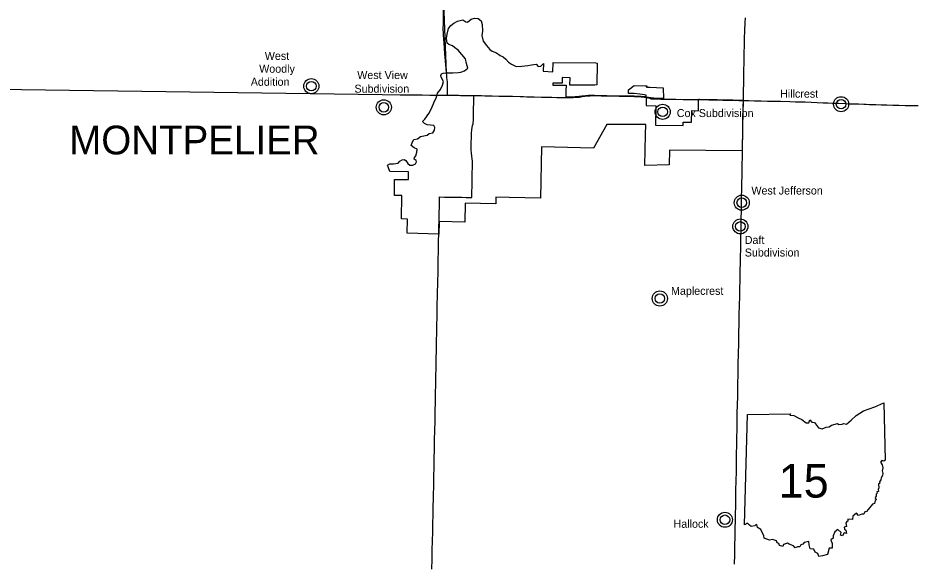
# Model space of a CAD drawing. Extents: x -66 to 795, y 0 to 440.
# Drawn here: x 250.6 to 383.6, y 175.4 to 256.3 of the extents above; entities that cross this region are included whole.
import ezdxf

# ---------------------------------------------------------------- set-up
doc = ezdxf.new("R2010")
doc.units = 0
for name, color, linetype in [('DV_X_Corp_Line', 7, 'Continuous'), ('GM_X_Corporation_Text', 7, 'Continuous'), ('GM_X_State_Route', 7, 'Continuous'), ('GM_X_US_Route', 7, 'Continuous'), ('PV_P_Text', 7, 'Continuous'), ('RD_P_Fence', 7, 'Continuous')]:
    doc.layers.add(name, color=color, linetype=linetype)

msp = doc.modelspace()

# ---------------------------------------------------------------- linework, layer by layer
at = {"layer": 'DV_X_Corp_Line'}
msp.add_lwpolyline([(358.16, 240.24), (358.16, 240.08), (358.12, 238.6), (358.11, 237.76), (358.11, 237.68), (358.1, 237.15), (358.1, 236.81), (358.09, 236.57), (347.3, 236.7), (347.25, 234.52), (343.65, 234.43), (343.75, 238.98), (343.78, 240.5), (337.99, 240.49), (336.03, 236.98), (328.3, 237.19), (328.17, 229.58), (323.52, 229.66), (321.55, 229.69), (321.54, 228.72), (316.97, 228.82), (316.93, 226), (313.12, 226.1), (313.12, 225.97), (313.11, 225.89), (313.08, 224.34), (313.08, 224.2), (308.36, 224.36), (308.41, 226.44), (307.55, 226.48), (307.59, 229.94), (306.49, 229.96), (306.51, 232.33), (308.58, 232.35), (308.56, 233.48), (305.82, 233.54), (305.61, 234.09), (305.47, 234.46), (305.8, 234.68), (306.33, 234.66), (307.02, 234.77), (307.28, 235.05), (307.63, 235.26), (307.92, 235.29), (308.16, 235.16), (308.46, 234.7), (308.78, 234.44), (309.23, 234.48), (309.6, 234.68), (309.73, 234.94), (309.69, 235.13), (309.39, 235.34), (309.45, 235.58), (309.65, 235.86), (309.78, 236.37), (309.87, 236.84), (309.42, 237.05), (308.96, 237.36), (309.17, 237.92), (309.35, 238.25), (309.9, 238.35), (310.34, 238.72), (311.33, 238.92), (311.65, 239.16), (312.16, 239.28), (312.45, 239.67), (312.48, 240.07), (312.33, 240.36), (311.82, 240.42), (311.34, 240.46), (310.94, 240.66), (310.73, 240.84), (310.66, 240.95), (311, 241.29), (311.58, 242.11), (311.97, 242.88), (312.33, 243.69), (312.67, 244.48), (312.81, 244.92), (312.89, 245.14), (313.33, 245.67), (313.63, 246.34), (313.78, 246.9), (313.43, 247.52), (313.39, 247.77), (313.47, 248), (313.7, 248.1), (314.22, 248.15), (314.21, 248.25), (314.29, 248.19), (315.14, 248.18), (315.99, 248.2), (316.35, 248.26), (316.87, 248.45), (317.38, 248.85), (317.19, 249.57), (317.05, 250.25), (316.49, 250.87), (315.92, 251.52), (315.4, 251.94), (315.12, 252.16), (314.56, 252.37), (314.29, 252.59), (314.21, 253.27), (314.33, 253.89), (314.51, 254.74), (314.84, 255.19), (315.29, 255.54), (315.84, 255.83), (316.62, 256.06), (317.07, 255.73), (317.3, 255.69), (317.86, 256.12), (318.38, 256.29), (318.9, 256.23), (319.34, 255.89), (319.52, 255.32), (319.54, 254.34), (319.45, 253.69), (319.63, 252.89), (320.15, 252.23), (320.63, 251.63), (320.98, 251.38), (321.63, 251.15), (322.19, 250.76), (322.61, 250.54), (323, 250.21), (323.39, 249.74), (323.86, 249.43), (324.55, 249.11), (325.39, 249.17), (326.29, 249.25), (326.81, 249.35), (327.18, 249.42), (327.52, 249.45), (327.81, 249.09), (328.21, 249.17), (328.6, 249.56), (328.57, 248.44), (330, 248.33), (330.02, 249.71), (336.35, 249.63), (336.56, 249.62), (336.5, 246.38), (336.23, 246.35), (332.53, 246.34), (332.55, 247.42), (331.37, 247.46), (331.37, 246.65), (330, 246.62), (330, 246.34), (331.97, 246.34), (331.93, 245.48), (331.91, 244.6), (332.38, 244.61), (332.76, 244.62), (333.28, 244.65), (333.44, 244.67), (334.3, 244.76), (334.44, 244.77), (334.83, 244.8), (335.27, 244.83), (335.59, 244.85), (336.19, 244.85), (338.02, 244.81), (340.06, 244.76), (341.15, 244.77), (342.07, 244.76), (343.09, 244.69), (343.61, 244.64), (343.84, 244.64), (343.85, 244.87), (343.57, 244.89), (342.91, 244.99), (342.07, 245.08), (341.23, 245.09), (341.24, 245.64), (342.04, 246.27), (343.68, 246.25), (343.92, 246.25), (343.91, 246.06), (344.37, 246.04), (346.38, 245.96), (346.43, 244.34), (346.2, 244.34), (345.24, 244.37), (344.96, 244.4), (344.51, 244.46), (343.87, 244.55), (343.86, 244.09), (343.85, 243.3), (345.27, 243.27), (345.23, 240.4), (349.35, 240.35), (349.35, 240.85), (350.59, 240.83), (350.63, 242.58), (351.61, 242.53), (351.62, 244.25), (351.76, 244.24), (352.16, 244.23), (353.14, 244.22), (354.37, 244.19), (355.66, 244.16), (356.68, 244.14), (357.6, 244.12), (358.23, 244.12)], close=True, dxfattribs=at)
for centre, radius in [((294.14, 246.19), 1.12), ((294.14, 246.19), 0.71), ((304.9, 243.05), 1.12), ((304.9, 243.05), 0.71), ((346.29, 242.38), 1.12), ((372.77, 243.51), 1.12), ((372.77, 243.51), 0.71), ((346.29, 242.38), 0.71), ((358.03, 228.89), 1.12), ((358.03, 228.89), 0.71), ((357.82, 225.37), 1.12), ((357.82, 225.37), 0.71), ((345.87, 214.67), 1.12), ((345.87, 214.67), 0.71), ((355.53, 181.82), 1.12), ((355.53, 181.82), 0.71)]:
    msp.add_circle(centre, radius, dxfattribs=at)
at = {"layer": 'GM_X_State_Route'}
msp.add_line((224.27, 246.03), (308.22, 244.92), dxfattribs=at)
for points in [[(314.22, 248.17), (314.16, 248.78), (314.06, 249.96), (313.97, 250.99), (313.91, 251.77), (313.84, 252.59), (313.79, 253.21), (313.76, 253.69), (313.74, 254.12), (313.73, 254.63), (313.74, 255.53), (313.77, 256.79), (313.79, 258.34), (313.81, 259.46), (313.81, 259.94), (313.81, 260.45), (313.85, 262.15), (313.88, 263.44), (313.91, 264.81), (313.93, 266), (313.95, 267.26), (313.98, 268.62), (314.01, 269.72), (314.02, 270.11)], [(314.38, 244.85), (314.38, 245.46), (314.38, 245.48), (314.37, 246.12), (314.37, 246.17), (314.36, 246.39), (314.34, 246.77), (314.34, 246.83), (314.28, 247.43), (314.25, 247.77), (314.22, 248.17), (314.22, 248.17)], [(307.31, 244.92), (307.31, 244.92), (308.22, 244.92), (309.36, 244.9), (310.6, 244.89), (311.75, 244.87), (312.46, 244.87), (312.53, 244.86), (312.53, 244.86)], [(312.53, 244.86), (312.84, 244.86), (312.84, 244.86)], [(312.84, 244.86), (313.14, 244.86), (313.15, 244.86)], [(313.15, 244.86), (313.45, 244.86), (314.38, 244.85)], [(314.38, 244.85), (315.05, 244.85), (315.26, 244.85), (316.03, 244.83), (316.28, 244.82), (316.98, 244.81), (317.22, 244.81), (318, 244.8), (318.26, 244.8)], [(317.97, 229.66), (317.99, 230.63), (318, 231.14), (318.01, 231.63), (318.02, 232.04), (318.03, 232.55), (318.03, 232.94), (318.04, 233.58), (318.05, 233.85), (318.06, 234.78), (318.05, 235.06), (318.02, 235.38), (317.96, 235.78), (317.91, 236.26), (317.88, 236.74), (317.86, 237.25), (317.87, 237.84), (317.9, 238.53), (317.94, 239.2), (317.97, 239.69), (318.01, 240.05), (318.06, 240.34), (318.15, 240.58), (318.19, 241.26), (318.21, 241.88), (318.21, 241.95), (318.22, 242.82), (318.24, 243.76), (318.24, 243.81), (318.26, 244.8)], [(318.26, 244.8), (319.03, 244.79), (319.27, 244.78), (319.4, 244.78), (319.91, 244.77), (320.05, 244.77), (320.21, 244.76), (320.99, 244.74), (321.99, 244.72), (322.19, 244.71), (322.73, 244.7), (323.08, 244.7), (323.75, 244.69), (323.98, 244.68), (325.15, 244.66), (325.21, 244.65), (325.63, 244.64), (325.64, 244.64)], [(331.97, 244.51), (332.99, 244.49), (333.93, 244.58), (334.34, 244.66), (334.76, 244.71), (335.28, 244.75), (335.54, 244.77), (336.17, 244.78), (337.18, 244.75), (338.03, 244.75), (338.66, 244.73), (339.85, 244.7), (341.01, 244.69), (341.16, 244.69)], [(325.64, 244.64), (326.15, 244.63), (327.2, 244.61), (328.32, 244.58), (328.55, 244.58), (329.26, 244.56)], [(329.26, 244.56), (329.44, 244.56), (329.53, 244.56), (329.85, 244.55), (329.86, 244.55)], [(329.86, 244.55), (330.59, 244.53), (331.66, 244.52), (331.67, 244.52)], [(331.67, 244.52), (331.95, 244.51), (331.97, 244.51)], [(341.16, 244.69), (342.06, 244.67), (343.09, 244.61), (343.58, 244.55), (343.79, 244.52)], [(343.79, 244.52), (343.94, 244.51)], [(343.94, 244.51), (344.18, 244.44), (344.59, 244.3), (345.1, 244.3), (345.76, 244.29), (346.04, 244.28), (346.33, 244.27)], [(346.33, 244.27), (346.49, 244.27), (347.03, 244.26), (347.09, 244.26)], [(347.09, 244.26), (348.22, 244.25), (349.33, 244.23), (350.48, 244.23), (351.76, 244.2), (352.16, 244.19), (353.14, 244.17), (353.71, 244.15)], [(353.71, 244.15), (354.41, 244.14), (355.21, 244.13)], [(355.21, 244.13), (355.67, 244.12), (356.68, 244.1), (357.6, 244.07), (357.62, 244.07)], [(357.62, 244.07), (358.22, 244.05)], [(358.22, 244.05), (358.19, 243.15)], [(358.19, 243.15), (358.18, 242.68), (358.16, 241.19), (358.16, 240.44)], [(358.16, 240.44), (358.16, 240.43), (358.16, 240.23), (358.16, 240.03), (358.14, 239.38)], [(358.14, 239.38), (358.13, 238.78), (358.12, 238.6), (358.11, 238.03), (358.11, 237.72)], [(358.1, 236.82), (358.08, 235.79), (358.06, 234.41), (358.03, 233.02), (358.01, 231.71), (357.99, 230.68), (357.96, 229.89), (357.96, 229.81), (357.94, 228.9), (357.92, 227.92), (357.92, 227.82), (357.89, 226.33), (357.88, 224.99), (357.86, 223.39), (357.82, 221.84), (357.81, 221.06), (357.78, 220.06), (357.76, 218.71), (357.73, 217.48), (357.69, 216.02), (357.67, 214.88), (357.63, 213.78), (357.61, 212.21), (357.58, 210.85), (357.55, 209.64), (357.52, 208.04), (357.5, 206.47), (357.46, 204.91), (357.44, 203.46), (357.41, 201.9), (357.38, 200.21), (357.35, 198.76), (357.32, 197.76), (357.31, 196.58), (357.29, 195.38), (357.25, 193.9), (357.24, 192.85), (357.21, 191.67), (357.19, 190.38), (357.18, 189.03), (357.14, 187.57), (357.12, 186.27), (357.1, 184.77), (357.08, 183.73), (357.05, 182.75), (357.03, 181.62), (357.02, 180.55), (357.02, 180.46), (356.98, 179.36), (356.96, 177.99), (356.94, 176.64), (356.91, 175.25)], [(358.11, 237.72), (358.11, 237.72), (358.1, 237.26), (358.1, 236.82), (358.1, 236.82)], [(313.1, 225.98), (313.12, 227.03), (313.15, 228.57), (313.17, 229.29), (313.18, 229.74)], [(313.18, 229.74), (313.9, 229.73), (314.1, 229.73), (314.7, 229.71), (315.45, 229.71), (315.52, 229.71), (316.34, 229.69), (316.46, 229.69), (317.15, 229.68), (317.97, 229.66)], [(313.03, 222.67), (313.04, 223.11), (313.07, 224.32), (313.09, 225.53), (313.1, 225.88), (313.1, 225.98)], [(312.62, 202.72), (312.63, 203.13), (312.65, 204.33), (312.68, 205.71), (312.7, 206.96), (312.74, 208.36), (312.77, 209.59), (312.78, 210.82), (312.8, 211.82), (312.82, 212.89), (312.84, 214.09), (312.86, 214.69), (312.87, 215.45), (312.91, 216.96), (312.95, 218.75), (312.98, 220.27), (313.01, 221.82), (313.02, 222.21), (313.03, 222.67)], [(312.57, 199.73), (312.59, 200.63), (312.61, 201.9), (312.62, 202.3), (312.62, 202.72)], [(312.05, 174.5), (312.08, 175.98), (312.1, 177.33), (312.13, 178.69), (312.17, 179.96), (312.19, 181.24), (312.21, 182.58), (312.25, 184.18), (312.26, 184.52), (312.27, 185.5), (312.31, 186.81), (312.33, 188.26), (312.36, 189.61), (312.39, 190.94), (312.42, 192.26), (312.45, 193.66), (312.48, 195.1), (312.51, 196.39), (312.53, 197.96), (312.56, 199.28), (312.57, 199.58), (312.57, 199.73)]]:
    msp.add_lwpolyline(points, dxfattribs=at)
at = {"layer": 'GM_X_US_Route'}
for points in [[(358.52, 256.35), (358.49, 255.62), (358.44, 254.39), (358.41, 253.3), (358.39, 252.27), (358.36, 251.08), (358.33, 249.75), (358.31, 248.47), (358.28, 247.24), (358.27, 246.6)], [(358.27, 246.6), (358.24, 245.55), (358.22, 244.05)], [(358.22, 244.05), (359.1, 244.04), (359.91, 244.03), (360.88, 244.01), (360.93, 244)], [(360.93, 244), (361.85, 243.98), (362.8, 243.96), (363.79, 243.94), (365.14, 243.91), (366, 243.88), (366.67, 243.86), (367.46, 243.84), (368.35, 243.8), (369.24, 243.77), (370.09, 243.73), (370.82, 243.71), (371.5, 243.68), (372.38, 243.65), (373.41, 243.61), (373.94, 243.59), (374.66, 243.57), (375.36, 243.55), (376.14, 243.52), (376.47, 243.51), (376.96, 243.49), (377.91, 243.47), (378.77, 243.44), (379.58, 243.42), (380.46, 243.39), (381.33, 243.37), (382.26, 243.34), (383.23, 243.32), (384.19, 243.3)]]:
    msp.add_lwpolyline(points, dxfattribs=at)
at = {"layer": 'PV_P_Text'}
msp.add_line((358.44, 181.06), (358.9, 197.43), dxfattribs=at)
for points in [[(358.9, 197.43), (365.26, 197.54), (365.16, 197.34), (365.76, 197.3), (366.39, 196.95), (366.93, 196.73), (367.59, 196.21), (367.98, 196.21), (368.15, 196.64), (368.45, 196.31), (368.81, 196.25), (369.43, 195.47), (369.94, 195.3), (370.55, 195.57), (371.01, 195.61), (371.35, 195.88), (372.22, 196.11), (372.46, 195.97), (372.92, 196), (373.15, 196.1), (373.56, 196.01), (374.27, 196.6), (374.99, 197.3), (376.12, 197.97), (377.79, 198.59), (379.12, 199.16), (379.31, 190.66)], [(379.31, 190.66), (379.11, 190.54), (378.81, 190.6), (378.6, 190.36), (378.86, 189.96), (378.98, 189.54), (378.87, 189.08), (378.98, 188.69), (378.9, 188.38), (378.71, 188.06), (378.65, 187.75), (378.48, 187.43), (378.5, 187.26), (378.34, 187.11), (378.37, 186.58), (378.29, 186.29), (378.32, 186.03), (378.07, 185.97), (378.13, 185.76), (377.97, 185.6), (378, 185.32), (377.82, 185.14), (377.99, 184.78), (377.85, 184.67), (377.74, 184.24), (377.41, 184.15), (376.77, 183.35), (376.54, 183.05), (376.28, 182.98), (376.14, 182.67), (375.83, 182.67), (375.35, 182.46), (375.04, 182.82), (374.5, 182.38), (374.44, 181.87), (373.75, 181.89), (373.78, 181.63), (373.63, 181.56), (373.49, 181.3), (373.57, 180.84), (373.25, 180.72), (373.29, 180.45), (373.49, 180.29), (373.59, 179.78), (373.25, 179.88), (372.97, 179.45), (372.68, 179.55), (372.77, 179.92), (372.29, 180.36), (371.83, 180.01), (371.59, 179.45), (371.59, 179.07), (371.25, 178.84), (371.47, 178.31), (371.43, 177.94), (371.44, 177.59), (371.01, 177.61), (370.75, 176.67)], [(370.75, 176.67), (370.01, 176.49), (369.49, 176.38), (369.31, 176.81), (368.94, 177.03), (368.71, 177.46), (368.18, 177.52), (368.05, 178.11), (367.99, 178.59), (367.27, 178.47), (367.07, 178.18), (366.82, 178.1), (366.67, 177.8), (366.32, 177.78), (365.94, 177.64), (365.7, 177.93), (365.08, 178.22), (364.81, 178.37), (364.23, 178.14), (364.11, 177.86), (363.65, 177.98), (363.54, 178.29), (363.26, 178.38), (363.2, 178.71), (362.61, 178.88), (362.15, 178.81), (361.35, 179.08), (361.3, 179.5), (361.03, 180.03), (360.88, 180.39), (360.38, 180.67), (360.27, 181.1), (360.11, 181.09), (359.96, 180.91), (359.4, 180.83), (359.18, 181.01), (358.86, 181.31), (358.44, 181.06)]]:
    msp.add_lwpolyline(points, dxfattribs=at)
at = {"layer": 'RD_P_Fence'}
msp.add_lwpolyline([(314.22, 248.17), (313.79, 258.55), (313.95, 266.77), (314.03, 270.76), (314.65, 273.62), (315.48, 277.07), (316.09, 304.15)], dxfattribs=at)

# ---------------------------------------------------------------- texts
at = {"layer": 'DV_X_Corp_Line'}
for s, height, p in [('West', 1.188, (287.24, 250.09)), ('Woodly', 1.188, (286.41, 248.18)), ('Addition', 1.188, (285.16, 246.24)), ('West View', 1.188, (300.96, 247.25)), ('Subdivision', 1.1875, (300.55, 245.22)), ('Hillcrest', 1.188, (363.72, 244.48)), ('Cox Subdivision', 1.1875, (348.39, 241.6)), ('West Jefferson', 1.1875, (359.46, 230.1)), ('Daft', 1.188, (358.47, 222.77)), ('Subdivision', 1.1875, (358.47, 220.9)), ('Maplecrest', 1.188, (347.53, 215.21)), ('Hallock', 1.188, (347.91, 180.63))]:
    msp.add_text(s, height=height, rotation=0, dxfattribs=at).set_placement(p)
at = {"layer": 'GM_X_Corporation_Text'}
msp.add_text('MONTPELIER', height=4.275, rotation=0, dxfattribs=at).set_placement((258.21, 236.06))
at = {"layer": 'PV_P_Text'}
msp.add_text('15', height=4.987, dxfattribs=at).set_placement((363.51, 185.11))

doc.saveas('drawing.dxf')
